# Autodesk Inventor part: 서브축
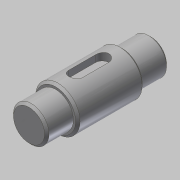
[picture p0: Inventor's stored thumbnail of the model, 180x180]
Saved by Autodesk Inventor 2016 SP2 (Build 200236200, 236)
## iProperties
Created: 2019-03
Part Number: 서브축
Material: 강철, 연강
Document SubType Name: Modeling
Designer: mduedu
Density: 1 g/cm^3
Appearance: 강철
Author: mduedu
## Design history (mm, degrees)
sketch "스케치1"
  geometry: L1 (0, 0)-(12, 0); L2 (12, 0)-(12, 8); L3 (12, 8)-(0, 8); L4 (0, 8)-(0, 0); L5 (12, 0)-(42, 0); L6 (42, 0)-(42, 10); L7 (42, 10)-(12, 10); L8 (12, 10)-(12, 0); L9 (42, 0)-(55, 0); L10 (55, 0)-(55, 8); L11 (55, 8)-(42, 8); L12 (42, 8)-(42, 0)
  constraints: 24 end point, 6 parallel, 3 horizontal, 3 perpendicular
  dimensions: "d0" = 16 diameter of L3 L1; "d2" = 20 diameter of L7 L5; "d3" = 16 diameter of L11 L9; "d4" = 12 distance of L2.end L3.end; "d5" = 30 distance of L6.end L7.end; "d6" = 55 distance between parallel lines of L10 L4
revolve "회전1" sketch "스케치1" stored, may be unused: angle "d7" = 90 deg
node "작업 평면1"
sketch "스케치2" dims "d10" = 18
  geometry: L1 (6, -3)-(-6, -3); L2 (-6, -3)-(-6, 3); L3 (-6, 3)-(6, 3); L4 (6, 3)-(6, -3); L5 (15, 10)-(15, -10) reference; 3 further points
  constraints: 8 end point, 2 midpoint, 2 parallel, 2 vertical alignment, 1 horizontal, 1 horizontal alignment, 1 perpendicular, 4 other
  dimensions: "d8" = 6 distance between parallel lines of L3 L1; "d11" = 6 dimension on L5
extrude "돌출1" cut sketch "스케치2" distance "d12" = 3.5; taper "d13" = 0 deg
chamfer "모따기1" distance "d14" = 1; stored, may be unused: second distance "d15" = 2, angle "d16" = 45 deg
chamfer "모따기2" distance "d17" = 1; stored, may be unused: second distance "d18" = 2, angle "d19" = 45 deg
node "솔리드1"
